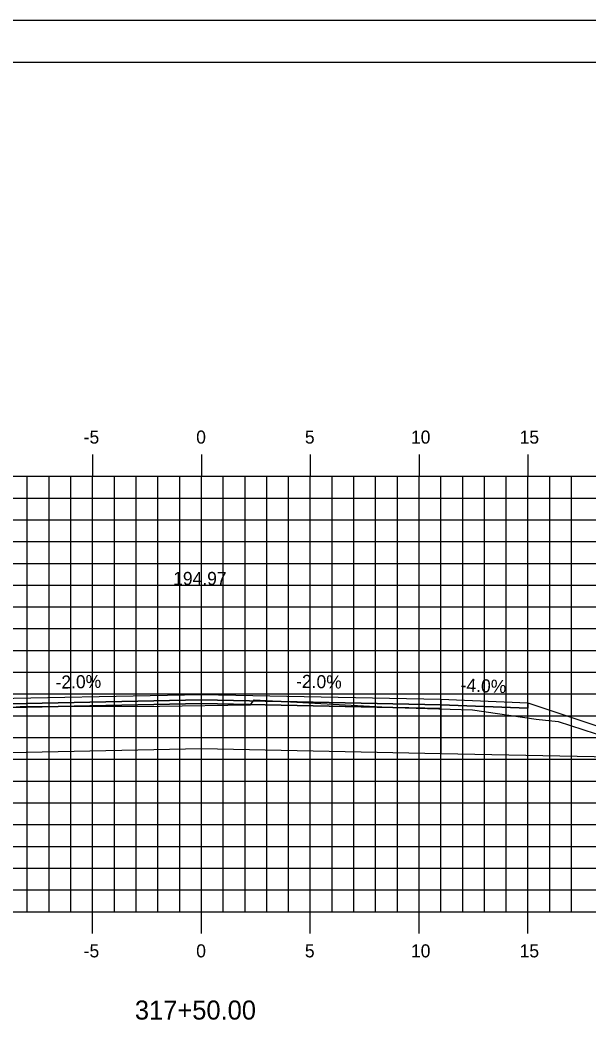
# Model space of a CAD drawing. Extents: x 1138985 to 1139155, y 608981 to 609091.
# Drawn here: x 1139059.63 to 1139085.73, y 609044.46 to 609091.28 of the extents above; entities that cross this region are included whole.
import ezdxf

# ---------------------------------------------------------------- set-up
doc = ezdxf.new("R2010")
doc.units = 0
for name, color, linetype in [('ANNOTATION', 7, 'Continuous'), ('BORDER', 7, 'Continuous'), ('D_Roadway_Centerline', 7, 'Continuous'), ('D_Roadway_Centerline_Text', 7, 'Continuous'), ('D_Roadway_Edge_Shoulder', 7, 'Continuous'), ('D_Roadway_Edge_TW', 7, 'Continuous'), ('D_Roadway_Pavement', 7, 'Continuous'), ('D_Roadway_SubGrade', 7, 'Continuous'), ('H_V ANNOTATION', 7, 'Continuous'), ('MAJOR', 7, 'Continuous'), ('MINOR', 7, 'Continuous'), ('PLOT BOUNDARY', 7, 'Continuous'), ('S_Roadway_Centerline', 7, 'Continuous')]:
    doc.layers.add(name, color=color, linetype=linetype)

msp = doc.modelspace()

# ---------------------------------------------------------------- linework, layer by layer
msp.add_lwpolyline([(1139032.911, 609059.91), (1139051.198, 609059.859), (1139051.199, 609059.859), (1139051.403, 609060.487), (1139051.699, 609060.499), (1139051.949, 609059.889), (1139056.949, 609060.089), (1139067.949, 609060.309), (1139078.949, 609060.089), (1139082.949, 609059.929), (1139090.672, 609057.354), (1139093.672, 609056.354), (1139094.967, 609057.001), (1139096.217, 609057.56), (1139097.467, 609057.986), (1139098.717, 609058.28), (1139099.967, 609058.441)])
at = {"layer": 'BORDER'}
msp.add_lwpolyline([(1138992.949, 608984.335), (1139152.949, 608984.335), (1139152.949, 609089.335), (1138992.949, 609089.335)], close=True, dxfattribs=at)
at = {"layer": 'D_Roadway_Edge_Shoulder'}
msp.add_lwpolyline([(1139078.949, 609060.089), (1139082.949, 609059.929), (1139082.949, 609059.679), (1139078.949, 609059.839)], close=True, dxfattribs=at)
at = {"layer": 'D_Roadway_Edge_TW'}
msp.add_lwpolyline([(1139056.949, 609059.839), (1139056.949, 609060.089), (1139067.949, 609060.309), (1139078.949, 609060.089), (1139078.949, 609059.839), (1139067.949, 609060.059)], close=True, dxfattribs=at)
at = {"layer": 'D_Roadway_Pavement'}
msp.add_lwpolyline([(1139056.949, 609059.672), (1139056.949, 609059.839), (1139067.949, 609060.059), (1139078.949, 609059.839), (1139078.949, 609059.672), (1139067.949, 609059.892)], close=True, dxfattribs=at)
at = {"layer": 'D_Roadway_SubGrade'}
for points in [[(1139056.949, 609057.589), (1139056.949, 609059.672), (1139067.949, 609059.892), (1139078.949, 609059.672), (1139078.949, 609057.589), (1139067.949, 609057.809)], [(1139078.949, 609059.672), (1139078.949, 609059.839), (1139082.949, 609059.679), (1139082.949, 609059.929), (1139082.949, 609059.929), (1139090.672, 609057.354), (1139078.949, 609057.589)]]:
    msp.add_lwpolyline(points, close=True, dxfattribs=at)
at = {"layer": 'MAJOR'}
for p, q in [((1139062.949, 609071.337), (1139062.949, 609070.335)), ((1139067.949, 609071.337), (1139067.949, 609070.335)), ((1139072.949, 609071.337), (1139072.949, 609070.335)), ((1139077.949, 609071.337), (1139077.949, 609070.335)), ((1139082.949, 609071.337), (1139082.949, 609070.335)), ((1138997.949, 609070.335), (1139137.949, 609070.335)), ((1138997.949, 609070.335), (1139137.949, 609070.335)), ((1139062.949, 609050.335), (1139062.949, 609070.335)), ((1139067.949, 609050.335), (1139067.949, 609070.335)), ((1139072.949, 609050.335), (1139072.949, 609070.335)), ((1139077.949, 609050.335), (1139077.949, 609070.335)), ((1139082.949, 609050.335), (1139082.949, 609070.335)), ((1138997.949, 609065.335), (1139137.949, 609065.335)), ((1138997.949, 609060.335), (1139137.949, 609060.335)), ((1138997.949, 609055.335), (1139137.949, 609055.335)), ((1138997.949, 609050.335), (1139137.949, 609050.335)), ((1138997.949, 609050.335), (1139137.949, 609050.335)), ((1139062.949, 609049.333), (1139062.949, 609050.335)), ((1139067.949, 609049.333), (1139067.949, 609050.335)), ((1139072.949, 609049.333), (1139072.949, 609050.335)), ((1139077.949, 609049.333), (1139077.949, 609050.335)), ((1139082.949, 609049.333), (1139082.949, 609050.335))]:
    msp.add_line(p, q, dxfattribs=at)
at = {"layer": 'MINOR'}
for p, q in [((1139059.949, 609050.335), (1139059.949, 609070.335)), ((1139060.949, 609050.335), (1139060.949, 609070.335)), ((1139061.949, 609050.335), (1139061.949, 609070.335)), ((1139063.949, 609050.335), (1139063.949, 609070.335)), ((1139064.949, 609050.335), (1139064.949, 609070.335)), ((1139065.949, 609050.335), (1139065.949, 609070.335)), ((1139066.949, 609050.335), (1139066.949, 609070.335)), ((1139068.949, 609050.335), (1139068.949, 609070.335)), ((1139069.949, 609050.335), (1139069.949, 609070.335)), ((1139070.949, 609050.335), (1139070.949, 609070.335)), ((1139071.949, 609050.335), (1139071.949, 609070.335)), ((1139073.949, 609050.335), (1139073.949, 609070.335)), ((1139074.949, 609050.335), (1139074.949, 609070.335)), ((1139075.949, 609050.335), (1139075.949, 609070.335)), ((1139076.949, 609050.335), (1139076.949, 609070.335)), ((1139078.949, 609050.335), (1139078.949, 609070.335)), ((1139079.949, 609050.335), (1139079.949, 609070.335)), ((1139080.949, 609050.335), (1139080.949, 609070.335)), ((1139081.949, 609050.335), (1139081.949, 609070.335)), ((1139083.949, 609050.335), (1139083.949, 609070.335)), ((1139084.949, 609050.335), (1139084.949, 609070.335)), ((1138997.949, 609069.335), (1139137.949, 609069.335)), ((1138997.949, 609068.335), (1139137.949, 609068.335)), ((1138997.949, 609067.335), (1139137.949, 609067.335)), ((1138997.949, 609066.335), (1139137.949, 609066.335)), ((1138997.949, 609064.335), (1139137.949, 609064.335)), ((1138997.949, 609063.335), (1139137.949, 609063.335)), ((1138997.949, 609062.335), (1139137.949, 609062.335)), ((1138997.949, 609061.335), (1139137.949, 609061.335)), ((1138997.949, 609059.335), (1139137.949, 609059.335)), ((1138997.949, 609058.335), (1139137.949, 609058.335)), ((1138997.949, 609057.335), (1139137.949, 609057.335)), ((1138997.949, 609056.335), (1139137.949, 609056.335)), ((1138997.949, 609054.335), (1139137.949, 609054.335)), ((1138997.949, 609053.335), (1139137.949, 609053.335)), ((1138997.949, 609052.335), (1139137.949, 609052.335)), ((1138997.949, 609051.335), (1139137.949, 609051.335))]:
    msp.add_line(p, q, dxfattribs=at)
at = {"layer": 'PLOT BOUNDARY'}
msp.add_lwpolyline([(1138984.856, 608981.276), (1139154.856, 608981.276), (1139154.856, 609091.276), (1138984.856, 609091.276)], close=True, dxfattribs=at)
at = {"layer": 'S_Roadway_Centerline'}
msp.add_lwpolyline([(1139016.434, 609060.334), (1139031.885, 609059.945), (1139034.377, 609059.859), (1139052.189, 609059.505), (1139054.799, 609059.411), (1139055.727, 609059.439), (1139059.616, 609059.763), (1139066.017, 609059.781), (1139070.197, 609059.83), (1139070.369, 609060.059), (1139076.793, 609059.71), (1139080.407, 609059.613), (1139083.326, 609059.173), (1139084.343, 609059.069), (1139087.733, 609057.962), (1139089.051, 609057.481), (1139090.872, 609057.361), (1139093.183, 609057.505), (1139095.448, 609057.872), (1139096.555, 609058.182), (1139104.125, 609058.757), (1139115.082, 609058.5), (1139137.949, 609058.777)], dxfattribs=at)

# ---------------------------------------------------------------- texts
at = {"layer": 'ANNOTATION'}
for s, rotation, p in [('-2.0%', 1.1458, (1139061.252, 609060.575)), ('-2.0%', 358.8542, (1139072.292, 609060.622)), ('-4.0%', 357.7094, (1139079.845, 609060.454))]:
    msp.add_text(s, height=0.6, rotation=rotation, dxfattribs=at).set_placement(p)
at = {"layer": 'D_Roadway_Centerline'}
for s, p in [('C', (1139067.943, 609060.309)), ('L', (1139067.949, 609060.301))]:
    msp.add_text(s, height=0.0146, dxfattribs=at).set_placement(p)
at = {"layer": 'D_Roadway_Centerline_Text'}
msp.add_text('194.97', height=0.6, dxfattribs=at).set_placement((1139066.649, 609065.341))
at = {"layer": 'H_V ANNOTATION'}
for s, height, p in [('-5', 0.6, (1139062.539, 609071.835)), ('0', 0.6, (1139067.708, 609071.835)), ('5', 0.6, (1139072.7, 609071.835)), ('10', 0.6, (1139077.574, 609071.835)), ('15', 0.6, (1139082.566, 609071.835)), ('-5', 0.6, (1139062.539, 609048.235)), ('0', 0.6, (1139067.708, 609048.235)), ('5', 0.6, (1139072.7, 609048.235)), ('10', 0.6, (1139077.574, 609048.235)), ('15', 0.6, (1139082.566, 609048.235)), ('317+50.00', 0.875, (1139064.89, 609045.378))]:
    msp.add_text(s, height=height, dxfattribs=at).set_placement(p)
at = {"layer": 'S_Roadway_Centerline'}
for s, p in [('C', (1139070.363, 609060.059)), ('L', (1139070.369, 609060.052))]:
    msp.add_text(s, height=0.0146, dxfattribs=at).set_placement(p)

doc.saveas('drawing.dxf')
